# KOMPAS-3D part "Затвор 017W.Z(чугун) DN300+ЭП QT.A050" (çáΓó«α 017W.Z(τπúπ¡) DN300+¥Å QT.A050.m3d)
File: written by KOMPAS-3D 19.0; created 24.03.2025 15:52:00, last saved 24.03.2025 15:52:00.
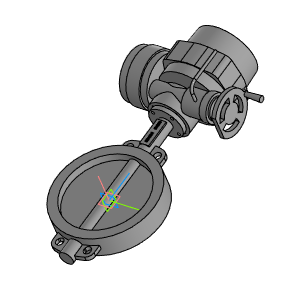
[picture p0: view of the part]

Document properties: Полное имя файла: Затвор 017W.Z(чугун) DN300+ЭП QT.A050.a3d

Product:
- Part/product: Затвор 017W.Z(чугун) DN300+ЭП QT.A050
    Масса: 153.799

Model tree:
1. Операция без истории:1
